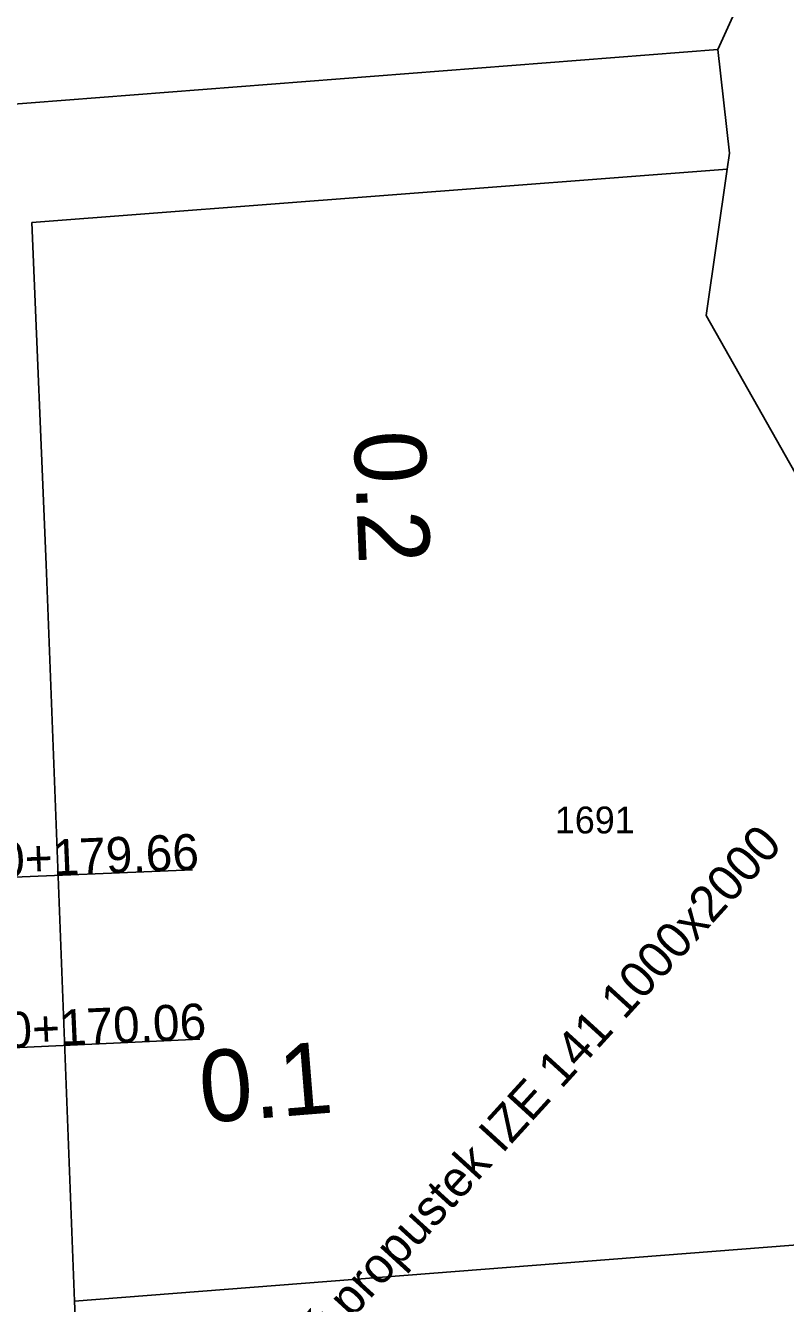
# Model space of a CAD drawing. Extents: x -583721 to -583071, y -1166145 to -1165065.
# Drawn here: x -583201.7 to -583159.2, y -1165972.3 to -1165900.9 of the extents above; entities that cross this region are included whole.
import ezdxf

# ---------------------------------------------------------------- set-up
doc = ezdxf.new("R2010")
doc.units = 0
for name, color, linetype in [('01_DOPRAVA', 7, 'Continuous'), ('Parcelní čísla', 7, 'Continuous'), ('TISK', 7, 'Continuous'), ('Trojúhelniky', 7, 'Continuous')]:
    doc.layers.add(name, color=color, linetype=linetype)

msp = doc.modelspace()

# ---------------------------------------------------------------- linework, layer by layer
at = {"layer": '01_DOPRAVA'}
for p, q in [((-583206.76, -1165905.62), (-583162.97, -1165902.22)), ((-583198.95, -1165972.17), (-583115.95, -1165965.7)), ((-583198.6, -1165981.46), (-583198.95, -1165972.17))]:
    msp.add_line(p, q, dxfattribs=at)
for points in [[(-583111.31, -1165711.19), (-583108.06, -1165725.24), (-583108.03, -1165738.33), (-583122.6, -1165772.66), (-583125.01, -1165781.15), (-583127.6, -1165810.04), (-583129.98, -1165835.69), (-583134.92, -1165854.65), (-583138.16, -1165860.06), (-583151.44, -1165876.82), (-583162.97, -1165902.22)], [(-583162.97, -1165902.22), (-583162.33, -1165908.01), (-583162.46, -1165908.91)], [(-583162.46, -1165908.91), (-583201.33, -1165911.89), (-583200.54, -1165931), (-583198.95, -1165972.17)], [(-583162.46, -1165908.91), (-583163.63, -1165917.08), (-583158.4, -1165926.3), (-583141.78, -1165942.82), (-583131.19, -1165952.38), (-583115.95, -1165965.7)]]:
    msp.add_lwpolyline(points, dxfattribs=at)
at = {"layer": 'TISK'}
for points in [[(-583217.328, -1165949.077), (-583192.349, -1165948.055)], [(-583216.912, -1165958.669), (-583191.939, -1165957.526)]]:
    msp.add_lwpolyline(points, dxfattribs=at)

# ---------------------------------------------------------------- texts
at = {"layer": 'Parcelní čísla'}
msp.add_text('1691', height=1.5, dxfattribs=at).set_placement((-583172.088, -1165946.026))
at = {"layer": 'TISK'}
for s, rotation, p in [('0+122 00 Rámový propustek IZE 141 1000x2000', 47.62542, (-583198.632, -1165989.836)), ('KT 0+179.66', 2.3443, (-583207.337, -1165948.668)), ('TK 0+170.06', 2.61933, (-583206.923, -1165958.212))]:
    msp.add_text(s, height=2, rotation=rotation, dxfattribs=at).set_placement(p)
at = {"layer": 'Trojúhelniky'}
for s, rotation, p in [('0.2', 272.3443, (-583183.342, -1165923.593)), ('0.1', 4.59077, (-583191.813, -1165962.209))]:
    msp.add_text(s, height=4, rotation=rotation, dxfattribs=at).set_placement(p)

doc.saveas('drawing.dxf')
